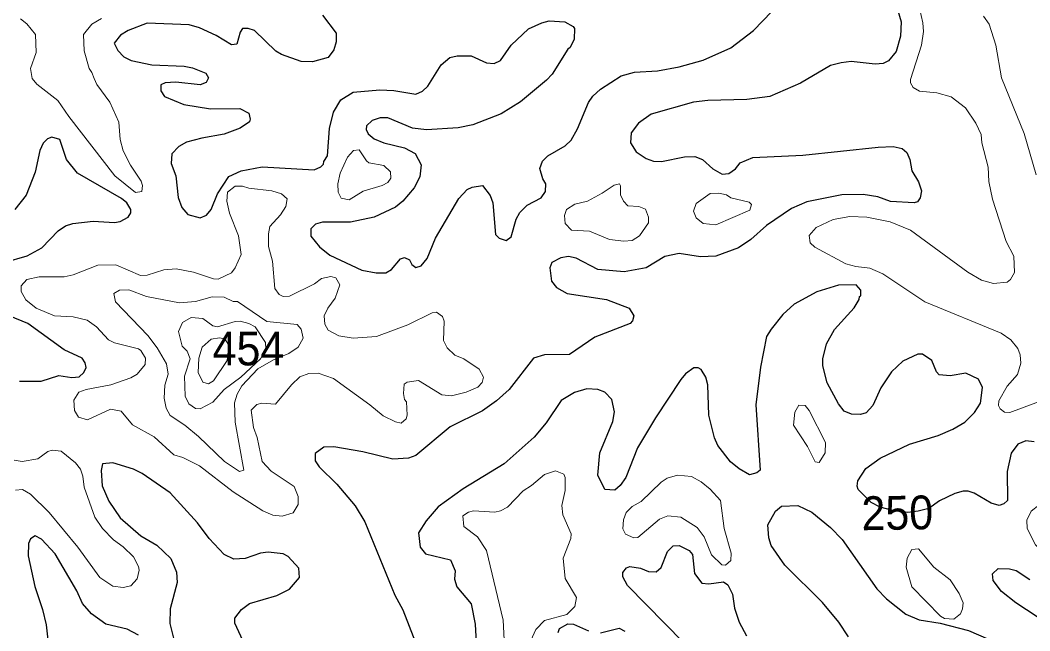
# Model space of a CAD drawing. Extents: x 763.2 to 816.8, y 7896.5 to 7952.7.
# Drawn here: x 791.41 to 796.187, y 7899.673 to 7902.563 of the extents above; entities that cross this region are included whole.
import ezdxf
from ezdxf.enums import TextEntityAlignment as Align

# ---------------------------------------------------------------- set-up
doc = ezdxf.new("R2010")
doc.units = 0
doc.header["$LTSCALE"] = 0.064
doc.layers.add('1', color=7, linetype='Continuous', lineweight=25)
doc.layers.add('2', color=7, linetype='Continuous', lineweight=13)
doc.layers.add('21', color=7, linetype='Continuous')
doc.layers.add('61', color=7, linetype='Continuous')

msp = doc.modelspace()

# ---------------------------------------------------------------- linework, layer by layer
at = {"layer": '1'}
for points in [[(793.4853, 7901.72), (793.5244, 7901.762), (793.5481, 7901.7722), (793.5969, 7901.7803), (793.634, 7901.7332), (793.6461, 7901.699), (793.6593, 7901.5488), (793.6763, 7901.5319), (793.7095, 7901.5197), (793.7331, 7901.5378), (793.7561, 7901.6207), (793.7737, 7901.6532), (793.8088, 7901.6882), (793.8748, 7901.7222), (793.8955, 7901.7529), (793.8972, 7901.7892), (793.8827, 7901.8116), (793.8679, 7901.8612), (793.8804, 7901.8955), (793.9067, 7901.9212), (793.9886, 7901.9679), (794.0161, 7901.9959), (794.0473, 7902.0495), (794.098, 7902.173), (794.1199, 7902.2044), (794.1555, 7902.237), (794.2536, 7902.3005), (794.3158, 7902.3174), (794.4247, 7902.323), (794.5284, 7902.3419), (794.6416, 7902.3747), (794.7726, 7902.4324), (794.8796, 7902.5144), (795.0528, 7902.6955)], [(795.548, 7902.6579), (795.5784, 7902.5551), (795.5752, 7902.4879), (795.555, 7902.4152), (795.5181, 7902.3709), (795.4932, 7902.3589), (795.4553, 7902.3557), (795.3416, 7902.3685), (795.2934, 7902.362), (795.2441, 7902.3493), (795.1013, 7902.2647), (794.9567, 7902.2025), (794.8482, 7902.1878), (794.6632, 7902.1839), (794.5958, 7902.1747), (794.3959, 7902.1188), (794.3358, 7902.0754), (794.3003, 7902.0299), (794.2971, 7901.9827), (794.3246, 7901.9403), (794.3717, 7901.9089), (794.4055, 7901.8964), (794.444, 7901.8937), (794.5524, 7901.9165), (794.6017, 7901.9182), (794.6374, 7901.9046), (794.6863, 7901.8592), (794.7314, 7901.8347), (794.7634, 7901.8381), (794.7946, 7901.8594), (794.8168, 7901.8886), (794.876, 7901.9134), (795.1127, 7901.925), (795.4686, 7901.9628), (795.5409, 7901.9656), (795.5829, 7901.9562), (795.6055, 7901.9367), (795.6196, 7901.9034), (795.6281, 7901.8501), (795.6606, 7901.7983), (795.6737, 7901.7556), (795.6685, 7901.7224), (795.6556, 7901.7033), (795.6394, 7901.6983), (795.528, 7901.7045), (795.4669, 7901.7276), (795.3978, 7901.7375), (795.2976, 7901.7372), (795.1309, 7901.7027), (795.0587, 7901.6714), (794.9413, 7901.5918), (794.8664, 7901.5251), (794.8078, 7901.4861), (794.701, 7901.4467)], [(792.8408, 7902.5872), (792.9044, 7902.5016), (792.9045, 7902.4616), (792.8947, 7902.423), (792.8666, 7902.3871), (792.7931, 7902.3657), (792.7398, 7902.3673), (792.6467, 7902.4008), (792.6197, 7902.4172), (792.5189, 7902.5143), (792.489, 7902.5246), (792.4618, 7902.5234), (792.4506, 7902.5068), (792.4353, 7902.4503), (792.4091, 7902.4465), (792.3376, 7902.491), (792.2579, 7902.5277), (792.2096, 7902.5411), (792.0108, 7902.5492), (791.9204, 7902.5148), (791.8849, 7902.4922), (791.8552, 7902.4542), (791.8716, 7902.4191), (791.9007, 7902.3901), (791.935, 7902.3731), (792.0324, 7902.3526), (792.1864, 7902.3451), (792.2247, 7902.3373), (792.288, 7902.3125), (792.3006, 7902.2908), (792.2903, 7902.2678), (792.2614, 7902.2571)], [(792.0936, 7902.2026), (792.1848, 7902.1638), (792.3108, 7902.1435), (792.4487, 7902.1452), (792.4922, 7902.1228), (792.4986, 7902.0943), (792.4955, 7902.0817), (792.451, 7902.0522), (792.3755, 7902.0231), (792.2687, 7902.0054), (792.1972, 7901.9858), (792.1604, 7901.9658), (792.1269, 7901.9312), (792.1243, 7901.8846), (792.1467, 7901.8263), (792.1569, 7901.7235), (792.1752, 7901.6774), (792.2028, 7901.6429), (792.2614, 7901.6277), (792.291, 7901.6403), (792.313, 7901.6669), (792.3435, 7901.7408), (792.3965, 7901.8239), (792.4555, 7901.8506), (792.5547, 7901.869), (792.8005, 7901.8543), (792.8322, 7901.8692), (792.8452, 7901.8825), (792.8464, 7901.8945), (792.8637, 7901.9216), (792.8741, 7902.0502), (792.8927, 7902.1287), (792.9278, 7902.1861), (792.9847, 7902.2219), (793.111, 7902.2338), (793.1785, 7902.2306), (793.2818, 7902.2129), (793.3129, 7902.2279), (793.3385, 7902.2504), (793.401, 7902.3527), (793.4423, 7902.3864), (793.4767, 7902.395), (793.5433, 7902.3949), (793.6165, 7902.3622), (793.6532, 7902.3576), (793.6825, 7902.3726), (793.7331, 7902.4454), (793.8153, 7902.5231), (793.8777, 7902.5515), (793.9129, 7902.5608), (793.9861, 7902.5551), (794.0257, 7902.534), (794.032, 7902.5234), (794.0305, 7902.473), (794.012, 7902.4333), (794.0014, 7902.4259), (793.9274, 7902.3085), (793.9001, 7902.2793), (793.7763, 7902.1768), (793.6849, 7902.1203), (793.5522, 7902.0683), (793.4824, 7902.0533), (793.332, 7902.045), (793.2664, 7902.0528), (793.1496, 7902.1005), (793.1129, 7902.1005), (793.076, 7902.0881), (793.0489, 7902.0638), (793.0462, 7902.0461), (793.0566, 7902.0247), (793.0842, 7902.0017), (793.13, 7901.9825), (793.2278, 7901.9596), (793.2782, 7901.9322), (793.307, 7901.878), (793.3006, 7901.8222), (793.2737, 7901.7704), (793.2208, 7901.7069), (793.1858, 7901.6785), (793.0846, 7901.6311), (792.9724, 7901.6073), (792.8407, 7901.6075), (792.808, 7901.5976), (792.785, 7901.5757), (792.7855, 7901.5408), (792.8261, 7901.4911), (792.8752, 7901.4517), (793.0265, 7901.38), (793.0937, 7901.3678), (793.1397, 7901.368), (793.1663, 7901.3835), (793.2095, 7901.4334), (793.228, 7901.4396), (793.2513, 7901.4283), (793.2636, 7901.4068)], [(792.2614, 7902.2571), (792.1458, 7902.2701), (792.0955, 7902.267), (792.0753, 7902.2578), (792.0752, 7902.229), (792.0936, 7902.2026)], [(791.3337, 7901.4164), (791.443, 7901.4482), (791.5118, 7901.4864), (791.5895, 7901.566), (791.6245, 7901.5895), (791.6591, 7901.6013), (791.756, 7901.6125), (791.8562, 7901.6062), (791.8827, 7901.6106), (791.9206, 7901.6314), (791.9343, 7901.6509), (791.9332, 7901.6669), (791.9146, 7901.6982), (791.8899, 7901.7185), (791.6808, 7901.839), (791.6292, 7901.9042), (791.5978, 7901.9984), (791.5604, 7902.0101), (791.5392, 7902.0019), (791.5189, 7901.9818), (791.503, 7901.947), (791.4812, 7901.8436), (791.4383, 7901.7353), (791.385, 7901.6674)], [(793.2636, 7901.4068), (793.2821, 7901.3932), (793.3073, 7901.401), (793.3356, 7901.4358), (793.3749, 7901.5321), (793.4853, 7901.72)], [(794.701, 7901.4467), (794.6287, 7901.4434), (794.5276, 7901.4596), (794.4606, 7901.4446), (794.3716, 7901.3906), (794.2672, 7901.3728)], [(794.2672, 7901.3728), (794.1429, 7901.3837), (794.0404, 7901.4366), (794.0042, 7901.4448), (793.9674, 7901.4381), (793.9251, 7901.4166), (793.9156, 7901.3908), (793.9231, 7901.3272), (793.9467, 7901.2972), (793.9977, 7901.2692), (794.1843, 7901.2414), (794.2919, 7901.2008), (794.3127, 7901.164), (794.3067, 7901.1402), (794.2953, 7901.1271), (794.1285, 7901.0633), (794.0082, 7900.9805), (793.8909, 7900.98), (793.8386, 7900.963), (793.7236, 7900.8146), (793.6643, 7900.7619), (793.5965, 7900.7142), (793.444, 7900.6387), (793.2826, 7900.5028), (793.2465, 7900.4899), (793.1729, 7900.4856), (793.0313, 7900.5197), (792.8932, 7900.5443), (792.8466, 7900.5423), (792.8058, 7900.5126), (792.8064, 7900.4771), (792.8249, 7900.4488), (792.908, 7900.3669), (792.9946, 7900.2639), (793.0403, 7900.1893), (793.1832, 7899.841), (793.2203, 7899.7719), (793.2804, 7899.6175)], [(796.207, 7900.567), (796.1678, 7900.5721), (796.1297, 7900.5564), (796.0983, 7900.5134), (796.08, 7900.4277), (796.0816, 7900.2895), (796.0643, 7900.2733), (796.0414, 7900.2654), (796.0034, 7900.2764), (795.9237, 7900.3242), (795.8954, 7900.3341), (795.8712, 7900.3339), (795.8325, 7900.3227), (795.7593, 7900.2887), (795.7088, 7900.252), (795.6582, 7900.2389), (795.6095, 7900.2323), (795.5327, 7900.2436), (795.4793, 7900.2576), (795.4354, 7900.2809), (795.3749, 7900.3422), (795.3702, 7900.3574), (795.3737, 7900.3824), (795.4111, 7900.4408), (795.4794, 7900.4897), (795.6181, 7900.5564), (795.7525, 7900.5966), (795.8219, 7900.6267), (795.8786, 7900.6611), (795.9252, 7900.7067), (795.9531, 7900.75), (795.9629, 7900.8248), (795.9432, 7900.8647), (795.8841, 7900.8918), (795.8095, 7900.8798), (795.7584, 7900.8846), (795.7446, 7900.8984), (795.7226, 7900.952), (795.6787, 7900.9828), (795.6568, 7900.9828), (795.5853, 7900.9487), (795.5327, 7900.8994), (795.4814, 7900.823), (795.4437, 7900.7401), (795.4129, 7900.7043), (795.3859, 7900.6973), (795.3428, 7900.6989), (795.3081, 7900.7118), (795.2809, 7900.7472), (795.2284, 7900.8473), (795.2075, 7900.9266), (795.2074, 7900.961), (795.2251, 7901.0318), (795.2631, 7901.0988), (795.3554, 7901.202), (795.3797, 7901.2406), (795.3815, 7901.2551), (795.3879, 7901.2591), (795.3879, 7901.286), (795.3645, 7901.3099), (795.2812, 7901.3086), (795.1792, 7901.2781), (795.0719, 7901.2193), (795.0183, 7901.1705), (794.9624, 7901.1015), (794.9414, 7901.0661), (794.9132, 7900.9215), (794.8904, 7900.7431), (794.9106, 7900.434), (794.8952, 7900.4205), (794.8604, 7900.4115), (794.8109, 7900.4399), (794.771, 7900.473), (794.7109, 7900.5494), (794.6945, 7900.5856), (794.6682, 7900.6939)], [(791.4062, 7900.8541), (791.5088, 7900.855), (791.5926, 7900.8808), (791.6541, 7900.8716), (791.6885, 7900.8746), (791.7118, 7900.8951), (791.7215, 7900.9194), (791.7179, 7900.9408), (791.7026, 7900.9637), (791.618, 7901.003), (791.4463, 7901.1281), (791.2679, 7901.1995)], [(794.5975, 7900.9172), (794.5578, 7900.8889), (794.5351, 7900.8632), (794.4155, 7900.6815), (794.3309, 7900.5389), (794.2753, 7900.3982), (794.2491, 7900.3602), (794.2237, 7900.3381), (794.1755, 7900.3425), (794.1423, 7900.4098), (794.152, 7900.5158), (794.2135, 7900.6642), (794.221, 7900.7097), (794.2099, 7900.7678), (794.1755, 7900.8019), (794.1423, 7900.8154), (794.0913, 7900.8187), (794.0323, 7900.8016), (793.9694, 7900.7624), (793.8987, 7900.6566), (793.8421, 7900.5893), (793.7002, 7900.4639), (793.5061, 7900.3449), (793.3876, 7900.2594), (793.3314, 7900.1941), (793.2945, 7900.1368), (793.3024, 7900.0692), (793.3269, 7900.0371), (793.4457, 7900.0095), (793.4679, 7899.9561), (793.4654, 7899.9175), (793.4756, 7899.881), (793.5437, 7899.7998), (793.5622, 7899.7039), (793.5704, 7899.5601)], [(794.6682, 7900.6939), (794.6633, 7900.8369), (794.6539, 7900.873), (794.6323, 7900.9098), (794.6172, 7900.9172), (794.5975, 7900.9172)], [(792.4822, 7899.5855), (792.4256, 7899.7096), (792.4259, 7899.733), (792.4566, 7899.7739), (792.495, 7899.8028), (792.6237, 7899.8394), (792.6845, 7899.8707), (792.7315, 7899.9258), (792.7278, 7899.969), (792.6786, 7900.0246), (792.6548, 7900.0367), (792.5826, 7900.0446), (792.5474, 7900.0396), (792.4751, 7900.0152), (792.421, 7900.0112), (792.3749, 7900.0335), (792.3037, 7900.1103), (792.249, 7900.1845), (792.1202, 7900.3262), (791.9877, 7900.4178), (791.9466, 7900.4375), (791.8487, 7900.4686), (791.7995, 7900.4639), (791.7939, 7900.431), (791.7987, 7900.3595), (791.8296, 7900.2871), (791.8838, 7900.2082)], [(795.3287, 7899.6447), (795.2824, 7899.713), (795.2051, 7899.8071), (795.0273, 7899.9835), (794.9637, 7900.0767), (794.9518, 7900.1136), (794.9477, 7900.1738), (794.9834, 7900.2392), (795.0113, 7900.2634), (795.0889, 7900.2665), (795.1552, 7900.235), (795.2439, 7900.1626), (795.2992, 7900.1055), (795.4632, 7899.8719), (795.5092, 7899.8238), (795.6007, 7899.752), (795.6634, 7899.7246), (795.7627, 7899.7095), (795.8958, 7899.6745), (796.1227, 7899.5772)], [(791.8838, 7900.2082), (791.9814, 7900.1231), (792.0565, 7900.0781), (792.1228, 7900.0149), (792.1502, 7899.951), (792.1532, 7899.9022)], [(791.9692, 7899.6519), (791.917, 7899.6814), (791.8152, 7899.7046), (791.7473, 7899.7528), (791.7043, 7899.802), (791.6775, 7899.8617), (791.5752, 7900.0366), (791.5117, 7900.1066), (791.481, 7900.1218), (791.4592, 7900.1075), (791.4491, 7900.0865), (791.4471, 7900.0283), (791.4799, 7899.8822), (791.516, 7899.7736), (791.5324, 7899.7013), (791.5423, 7899.6155)], [(794.5487, 7899.617), (794.2837, 7899.8871), (794.2608, 7899.9282), (794.2614, 7899.9489), (794.2783, 7899.9703), (794.2942, 7899.9773), (794.3453, 7899.9694), (794.383, 7899.9543), (794.4189, 7899.9519), (794.4432, 7899.9732), (794.4726, 7900.0489), (794.499, 7900.0758), (794.5284, 7900.0768), (794.5755, 7900.0532), (794.59, 7900.0344), (794.5995, 7899.9441), (794.6346, 7899.898), (794.6686, 7899.8951), (794.7371, 7899.9048), (794.7581, 7899.8908), (794.7798, 7899.8459), (794.7898, 7899.7803), (794.8115, 7899.7139), (794.8457, 7899.6496)], [(796.221, 7899.7396), (796.121, 7899.8049), (796.053, 7899.8596), (796.0129, 7899.9104), (796.0095, 7899.9427), (796.037, 7899.9676), (796.0907, 7899.966), (796.1226, 7899.958), (796.1869, 7899.9159)], [(792.1532, 7899.9022), (792.1198, 7899.7766), (792.1177, 7899.7072), (792.1454, 7899.6002)], [(793.955, 7899.6655), (793.9619, 7899.683), (794.0017, 7899.706), (794.0279, 7899.7041), (794.0988, 7899.6721)], [(794.1554, 7899.6638), (794.2435, 7899.6846), (794.2706, 7899.6713)]]:
    msp.add_lwpolyline(points, dxfattribs=at)
at = {"layer": '2'}
for points in [[(795.6567, 7902.6543), (795.6805, 7902.5503), (795.6837, 7902.5102)], [(791.7944, 7902.5719), (791.7484, 7902.5443), (791.7102, 7902.4959), (791.7128, 7902.4186), (791.7363, 7902.335), (791.7494, 7902.3151), (791.7594, 7902.2875), (791.7726, 7902.2591), (791.8336, 7902.1757), (791.8776, 7902.0803), (791.8824, 7901.9986), (791.8969, 7901.9445), (791.9314, 7901.8775), (791.9827, 7901.8012), (791.9892, 7901.7812), (791.9861, 7901.7519), (791.9551, 7901.7478), (791.8584, 7901.8259), (791.64, 7902.107), (791.5878, 7902.1834), (791.4885, 7902.2603), (791.467, 7902.2869), (791.4586, 7902.3346), (791.4864, 7902.4104), (791.4828, 7902.4962), (791.4414, 7902.5465), (791.4109, 7902.5701)], [(796.2162, 7901.8319), (796.1599, 7902.0264), (796.0525, 7902.2901), (796.0257, 7902.4452), (795.9946, 7902.5439), (795.9669, 7902.5816)], [(795.6837, 7902.5102), (795.6738, 7902.4451), (795.6218, 7902.2829), (795.6215, 7902.266), (795.6348, 7902.2454), (795.6647, 7902.2275)], [(795.6647, 7902.2275), (795.7463, 7902.219), (795.8146, 7902.2011), (795.882, 7902.1491), (795.9316, 7902.0751), (795.9565, 7902.0226), (795.96, 7901.9824), (795.9893, 7901.8681), (795.9926, 7901.7998), (796.0093, 7901.7163), (796.075, 7901.5158), (796.1109, 7901.4466), (796.1144, 7901.369), (796.0946, 7901.3365), (796.0788, 7901.3225), (796.0142, 7901.3176), (795.9581, 7901.3327), (795.8936, 7901.3699), (795.6224, 7901.5686), (795.5267, 7901.6091), (795.4157, 7901.6305), (795.3354, 7901.634), (795.2566, 7901.6191), (795.1761, 7901.5826), (795.142, 7901.5434), (795.1482, 7901.5099), (795.1689, 7901.4888), (795.3158, 7901.4106), (795.3632, 7901.3971), (795.43, 7901.3893), (795.4918, 7901.3634), (795.6898, 7901.2301), (796.0513, 7901.0821), (796.0973, 7901.051), (796.1298, 7901.0096), (796.1408, 7900.9793), (796.1438, 7900.9405), (796.1276, 7900.8855), (796.0799, 7900.8303), (796.0397, 7900.7611), (796.039, 7900.7397), (796.046, 7900.7231), (796.0664, 7900.7071), (796.0919, 7900.7058), (796.2584, 7900.7677)], [(792.5843, 7901.5525), (792.5908, 7901.5863), (792.6424, 7901.6425), (792.6673, 7901.682), (792.6725, 7901.7179), (792.6467, 7901.7408), (792.6, 7901.7558), (792.4912, 7901.7679), (792.4612, 7901.777), (792.4272, 7901.777), (792.3906, 7901.7485), (792.3871, 7901.7064), (792.4007, 7901.6505), (792.4435, 7901.5427), (792.456, 7901.454), (792.4276, 7901.3903), (792.4095, 7901.3678), (792.3466, 7901.3379), (792.3239, 7901.3384), (792.2293, 7901.3699), (792.1481, 7901.3859), (792.0894, 7901.3812), (792.0114, 7901.3568), (791.9791, 7901.3547), (791.8626, 7901.4053), (791.7782, 7901.4041), (791.6607, 7901.358), (791.6184, 7901.3488), (791.5003, 7901.3481), (791.4421, 7901.3362), (791.4145, 7901.3052), (791.4142, 7901.2798), (791.4361, 7901.2392), (791.486, 7901.2004), (791.572, 7901.164), (791.6614, 7901.1589), (791.7264, 7901.1441), (791.7712, 7901.1124), (791.8273, 7901.0503), (791.8565, 7901.0353), (791.9693, 7901.0077), (791.9802, 7901.0001), (792.0023, 7900.963), (792.0017, 7900.933), (791.9636, 7900.8874), (791.9335, 7900.8697), (791.8382, 7900.837), (791.7225, 7900.8153), (791.6872, 7900.8023), (791.6645, 7900.7654), (791.6674, 7900.716), (791.6861, 7900.6849), (791.7284, 7900.671), (791.8375, 7900.7217), (791.8879, 7900.7131), (791.9418, 7900.6482), (792.0446, 7900.5907), (792.1378, 7900.5051), (792.18, 7900.4934), (792.2589, 7900.454), (792.4177, 7900.3312), (792.5581, 7900.2404), (792.6047, 7900.2205), (792.65, 7900.2158), (792.7013, 7900.2313), (792.725, 7900.2704), (792.7255, 7900.3086), (792.7056, 7900.3566), (792.597, 7900.4285), (792.5549, 7900.474), (792.5318, 7900.5881), (792.5135, 7900.6355), (792.5024, 7900.7178), (792.5295, 7900.7449), (792.5531, 7900.7499), (792.6183, 7900.7464), (792.6932, 7900.8375), (792.7332, 7900.8746), (792.7749, 7900.891), (792.8202, 7900.8928), (792.8923, 7900.8667), (793.0641, 7900.7432), (793.1273, 7900.6904), (793.1852, 7900.6614), (793.2126, 7900.6562), (793.2365, 7900.6761), (793.2414, 7900.6933), (793.2383, 7900.7566), (793.2283, 7900.7674), (793.2236, 7900.7969), (793.2269, 7900.8411), (793.2408, 7900.8502), (793.2941, 7900.8581), (793.4053, 7900.7898), (793.4513, 7900.7844)], [(793.5815, 7900.9107), (793.5085, 7900.9598), (793.4659, 7900.978), (793.4307, 7901.0118), (793.4126, 7901.0472), (793.4155, 7901.1382), (793.4074, 7901.1604), (793.38, 7901.1817), (793.3585, 7901.1779), (793.2441, 7901.1206), (793.0952, 7901.0667), (792.9848, 7901.0576), (792.9173, 7901.0695), (792.8678, 7901.0967), (792.8508, 7901.1246), (792.8475, 7901.1639), (792.8654, 7901.2001), (792.9001, 7901.2468), (792.9224, 7901.3105), (792.9029, 7901.3439), (792.8795, 7901.3495), (792.835, 7901.34), (792.8018, 7901.3156), (792.6843, 7901.2566), (792.6545, 7901.2561), (792.6361, 7901.2656), (792.6141, 7901.2931), (792.604, 7901.4229), (792.5845, 7901.4913), (792.5843, 7901.5525)], [(793.4513, 7900.7844), (793.5203, 7900.8023), (793.575, 7900.8261), (793.5961, 7900.8477), (793.6015, 7900.8734), (793.5815, 7900.9107)], [(791.3813, 7900.4804), (791.42, 7900.4738), (791.4929, 7900.487), (791.5402, 7900.5209), (791.5607, 7900.5277), (791.6035, 7900.5225), (791.6721, 7900.4686), (791.6951, 7900.4376), (791.7064, 7900.4053), (791.7125, 7900.3523), (791.7639, 7900.2115), (791.8001, 7900.1571), (791.8509, 7900.1029), (791.8973, 7900.0711), (791.9462, 7900.0223), (791.9695, 7899.9774), (791.9727, 7899.9592), (791.9635, 7899.9195), (791.9331, 7899.8856), (791.898, 7899.8773), (791.8487, 7899.8838), (791.7873, 7899.9249), (791.6829, 7900.0682), (791.5473, 7900.2321), (791.4585, 7900.3192), (791.4208, 7900.3421), (791.3873, 7900.3381)], [(793.7043, 7899.5358), (793.6952, 7899.7236), (793.6161, 7900.0537), (793.5739, 7900.1183), (793.5084, 7900.1663), (793.5047, 7900.2167), (793.5309, 7900.2352), (793.5547, 7900.2404), (793.6559, 7900.2338), (793.6831, 7900.2408), (793.7155, 7900.2589), (793.7895, 7900.3361), (793.8294, 7900.36), (793.8908, 7900.4129), (793.943, 7900.4308), (793.9826, 7900.4142), (793.9877, 7900.3989), (793.9877, 7900.3366), (793.9732, 7900.2668), (793.978, 7900.2214), (794.0172, 7900.1312), (794.0149, 7900.1098), (793.9797, 7900.016), (793.9881, 7899.9201), (794.0416, 7899.8301), (794.0339, 7899.7876), (793.9958, 7899.7508), (793.8906, 7899.7222), (793.8495, 7899.6793), (793.786, 7899.5409)]]:
    msp.add_lwpolyline(points, dxfattribs=at)
for points in [[(792.9589, 7901.9156), (792.9875, 7901.9469), (793.0143, 7901.9495), (793.0484, 7901.8969), (793.0599, 7901.8886), (793.1298, 7901.8753), (793.1626, 7901.8452), (793.1643, 7901.8155), (793.1488, 7901.7949), (793.1225, 7901.7805), (793.032, 7901.7541), (792.9669, 7901.7134), (792.9286, 7901.7212), (792.9148, 7901.7491), (792.9131, 7901.7892), (792.9244, 7901.8398)], [(794.0342, 7901.6931), (794.0933, 7901.7066), (794.163, 7901.7438), (794.2199, 7901.7828), (794.2451, 7901.7882), (794.2506, 7901.7794), (794.2509, 7901.737), (794.264, 7901.7064), (794.2847, 7901.6852), (794.3369, 7901.6814), (794.3686, 7901.6687), (794.382, 7901.6314), (794.3821, 7901.6034), (794.3407, 7901.5421), (794.3052, 7901.5207), (794.2665, 7901.5174), (794.1988, 7901.5255), (794.1028, 7901.5649), (794.0188, 7901.5698), (793.988, 7901.6015), (793.9846, 7901.6392), (793.9947, 7901.6667)], [(794.7727, 7901.7231), (794.7523, 7901.7364), (794.7157, 7901.744), (794.6749, 7901.7422), (794.6085, 7901.6963), (794.5958, 7901.659), (794.6074, 7901.6276), (794.642, 7901.6013), (794.7017, 7901.5948), (794.8617, 7901.664), (794.8703, 7901.6903), (794.8596, 7901.7013)], [(792.4185, 7901.2317), (792.4377, 7901.231), (792.5768, 7901.1375), (792.7198, 7901.1224), (792.7402, 7901.101), (792.7483, 7901.0584), (792.7247, 7901.0151), (792.6817, 7900.9858), (792.6087, 7900.9558), (792.5351, 7900.9125), (792.4595, 7900.832), (792.4367, 7900.7932), (792.4233, 7900.7525), (792.4266, 7900.6612), (792.4682, 7900.4339), (792.4469, 7900.4264), (792.3761, 7900.4749), (792.2539, 7900.592), (792.1888, 7900.6459), (792.1204, 7900.6913), (792.1014, 7900.7266), (792.0906, 7900.7746), (792.0938, 7900.8353), (792.1104, 7900.8877), (792.1026, 7900.9372), (792.0587, 7901.0121), (792.0144, 7901.0713), (791.8617, 7901.2306), (791.8527, 7901.2703), (791.8803, 7901.2853), (791.9246, 7901.2873), (792.0081, 7901.2554), (792.1636, 7901.2248), (792.2401, 7901.2309), (792.3187, 7901.2543), (792.3758, 7901.2528)], [(792.2001, 7900.9959), (792.1771, 7901.0196), (792.1587, 7901.0889), (792.1778, 7901.1321), (792.2187, 7901.1553), (792.2747, 7901.1508), (792.3213, 7901.1165), (792.3443, 7901.1114), (792.4272, 7901.1377), (792.4502, 7901.1391), (792.4915, 7901.128), (792.5218, 7901.1124), (792.5711, 7901.0372), (792.5725, 7901.0064), (792.5469, 7900.9606), (792.4539, 7900.8741), (792.3745, 7900.8144), (792.3221, 7900.7544), (792.2618, 7900.7232), (792.2396, 7900.7252), (792.2072, 7900.7478), (792.1899, 7900.7833), (792.188, 7900.8777), (792.2142, 7900.9596)], [(792.3141, 7901.0539), (792.3532, 7901.06), (792.379, 7901.055), (792.3969, 7901.0244), (792.3895, 7900.9518), (792.3247, 7900.8556), (792.3008, 7900.842), (792.274, 7900.8499), (792.252, 7900.8951), (792.2557, 7900.9634), (792.2716, 7901.0151)], [(795.1428, 7900.7154), (795.1238, 7900.7392), (795.0943, 7900.7402), (795.0743, 7900.7071), (795.0688, 7900.6464), (795.1353, 7900.5454), (795.1711, 7900.4727), (795.19, 7900.4691), (795.2186, 7900.5154), (795.2202, 7900.565)], [(794.2738, 7900.1309), (794.2608, 7900.1557), (794.2639, 7900.1976), (794.2771, 7900.2321), (794.3055, 7900.2607), (794.348, 7900.2848), (794.4429, 7900.3769), (794.471, 7900.3948), (794.5195, 7900.4098), (794.5853, 7900.4032), (794.6314, 7900.3787), (794.6747, 7900.3439), (794.7237, 7900.2894), (794.7406, 7900.1576), (794.7732, 7900.0399), (794.7718, 7900.0052), (794.7464, 7899.9842), (794.7288, 7899.9853), (794.6812, 7900.0323), (794.6458, 7900.1174), (794.6124, 7900.1626), (794.5359, 7900.211), (794.4743, 7900.2172), (794.4343, 7900.2021), (794.3324, 7900.1153), (794.3131, 7900.1124)], [(796.3212, 7900.1168), (796.3146, 7900.1717), (796.2784, 7900.2614), (796.2661, 7900.2683), (796.2296, 7900.2681), (796.193, 7900.2399), (796.1732, 7900.1971), (796.1734, 7900.1565), (796.2127, 7900.0795), (796.2686, 7900.0281), (796.2826, 7899.9912), (796.3167, 7899.9595), (796.386, 7899.9592), (796.4253, 7899.983), (796.4352, 7900.006), (796.4335, 7900.0341), (796.4096, 7900.0651), (796.361, 7900.0779)], [(795.7326, 7899.9745), (795.6603, 7900.0607), (795.6277, 7900.0574), (795.606, 7900.017), (795.6018, 7899.9735), (795.6283, 7899.8807), (795.7644, 7899.7426), (795.7834, 7899.7316), (795.8273, 7899.7281), (795.8584, 7899.753), (795.8682, 7899.7765), (795.8708, 7899.8051), (795.8526, 7899.8498), (795.8102, 7899.9148)]]:
    msp.add_lwpolyline(points, close=True, dxfattribs=at)

# ---------------------------------------------------------------- texts
at = {"layer": '21', "width": 0.95}
msp.add_text('454', height=0.16, dxfattribs=at).set_placement((792.3205, 7900.9293))
at = {"layer": '61', "width": 0.95}
msp.add_text('250', height=0.16, rotation=0.909, dxfattribs=at).set_placement((795.5608, 7900.1515), align=Align.CENTER)

doc.saveas('drawing.dxf')
